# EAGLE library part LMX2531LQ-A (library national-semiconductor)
High Performance Frequency Synthesizer System with Integrated VCO Source: http://cache.national.com/ds/LM/LMX2531LQ1515E.pdf?
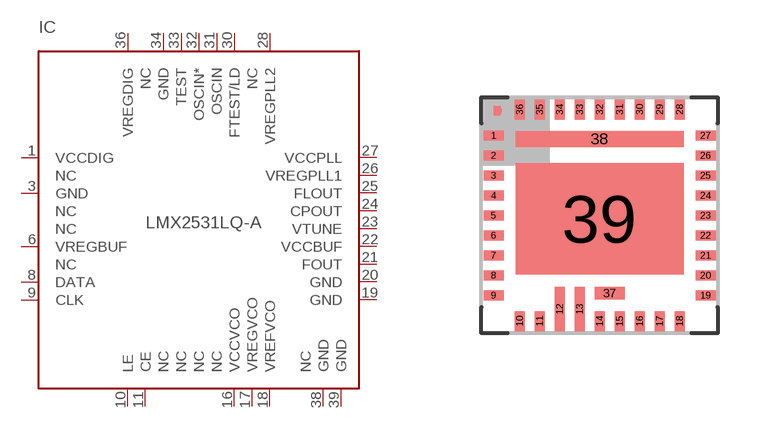
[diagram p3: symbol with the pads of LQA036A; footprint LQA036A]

Designator prefix IC

## LMX2531LQ-A (MPN: LMX2531LQ1515E; OC_FARNELL: 1609181; OC_NEWARK: 04R9133)  [LQA036A]
1  VCCDIG  pwr
2  NC  nc
3  GND  pwr
4  NC  nc
5  NC  nc
6  VREGBUF  in
7  NC  nc
8  DATA  in
9  CLK  in
10  LE  in
11  CE  in
12  NC  nc
13  NC  nc
14  NC  nc
15  NC  nc
16  VCCVCO  in
17  VREGVCO  pas
18  VREFVCO  pas
19  GND  pwr
20  GND  pwr
21  FOUT  out
22  VCCBUF  in
23  VTUNE  in
24  CPOUT  out
25  FLOUT  out
26  VREGPLL1  pas
27  VCCPLL  in
28  VREGPLL2  pas
29  NC  nc
30  FTEST/LD  out
31  OSCIN  in
32  OSCIN*  in
33  TEST  in
34  GND  pwr
35  NC  nc
36  VREGDIG  in
37  NC  nc
38  GND  pwr
39  GND  pwr

## Footprint LQA036A (pad centres in mm)
NS Package Number LQA036A Source: http://cache.national.com/ds/LM/LMX2531LQ1515E.pdf?
smd 0.5 x 0.25: 1 -2.65,2; 2 -2.65,1.5; 3 -2.65,1; 4 -2.65,0.5; 5 -2.65,0; 6 -2.65,-0.5; 7 -2.65,-1; 8 -2.65,-1.5; 9 -2.65,-2; 19 2.65,-2; 20 2.65,-1.5; 21 2.65,-1; 22 2.65,-0.5; 23 2.65,0; 24 2.65,0.5; 25 2.65,1; 26 2.65,1.5; 27 2.65,2
smd 0.25 x 0.5: 10 -2,-2.65; 11 -1.5,-2.65; 14 0,-2.65; 15 0.5,-2.65; 16 1,-2.65; 17 1.5,-2.65; 18 2,-2.65; 28 2,2.65; 29 1.5,2.65; 30 1,2.65; 31 0.5,2.65; 32 0,2.65; 33 -0.5,2.65; 34 -1,2.65; 35 -1.5,2.65; 36 -2,2.65
smd 0.25 x 1.11: 12 -1,-2.35; 13 -0.5,-2.35
smd 0.75 x 0.31: 37 0.25,-1.95
smd 4.2 x 0.4: 38 0,1.91
smd 4.2 x 2.79: 39 0,-0.09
